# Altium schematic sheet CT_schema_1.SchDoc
size 391 x 258 mm
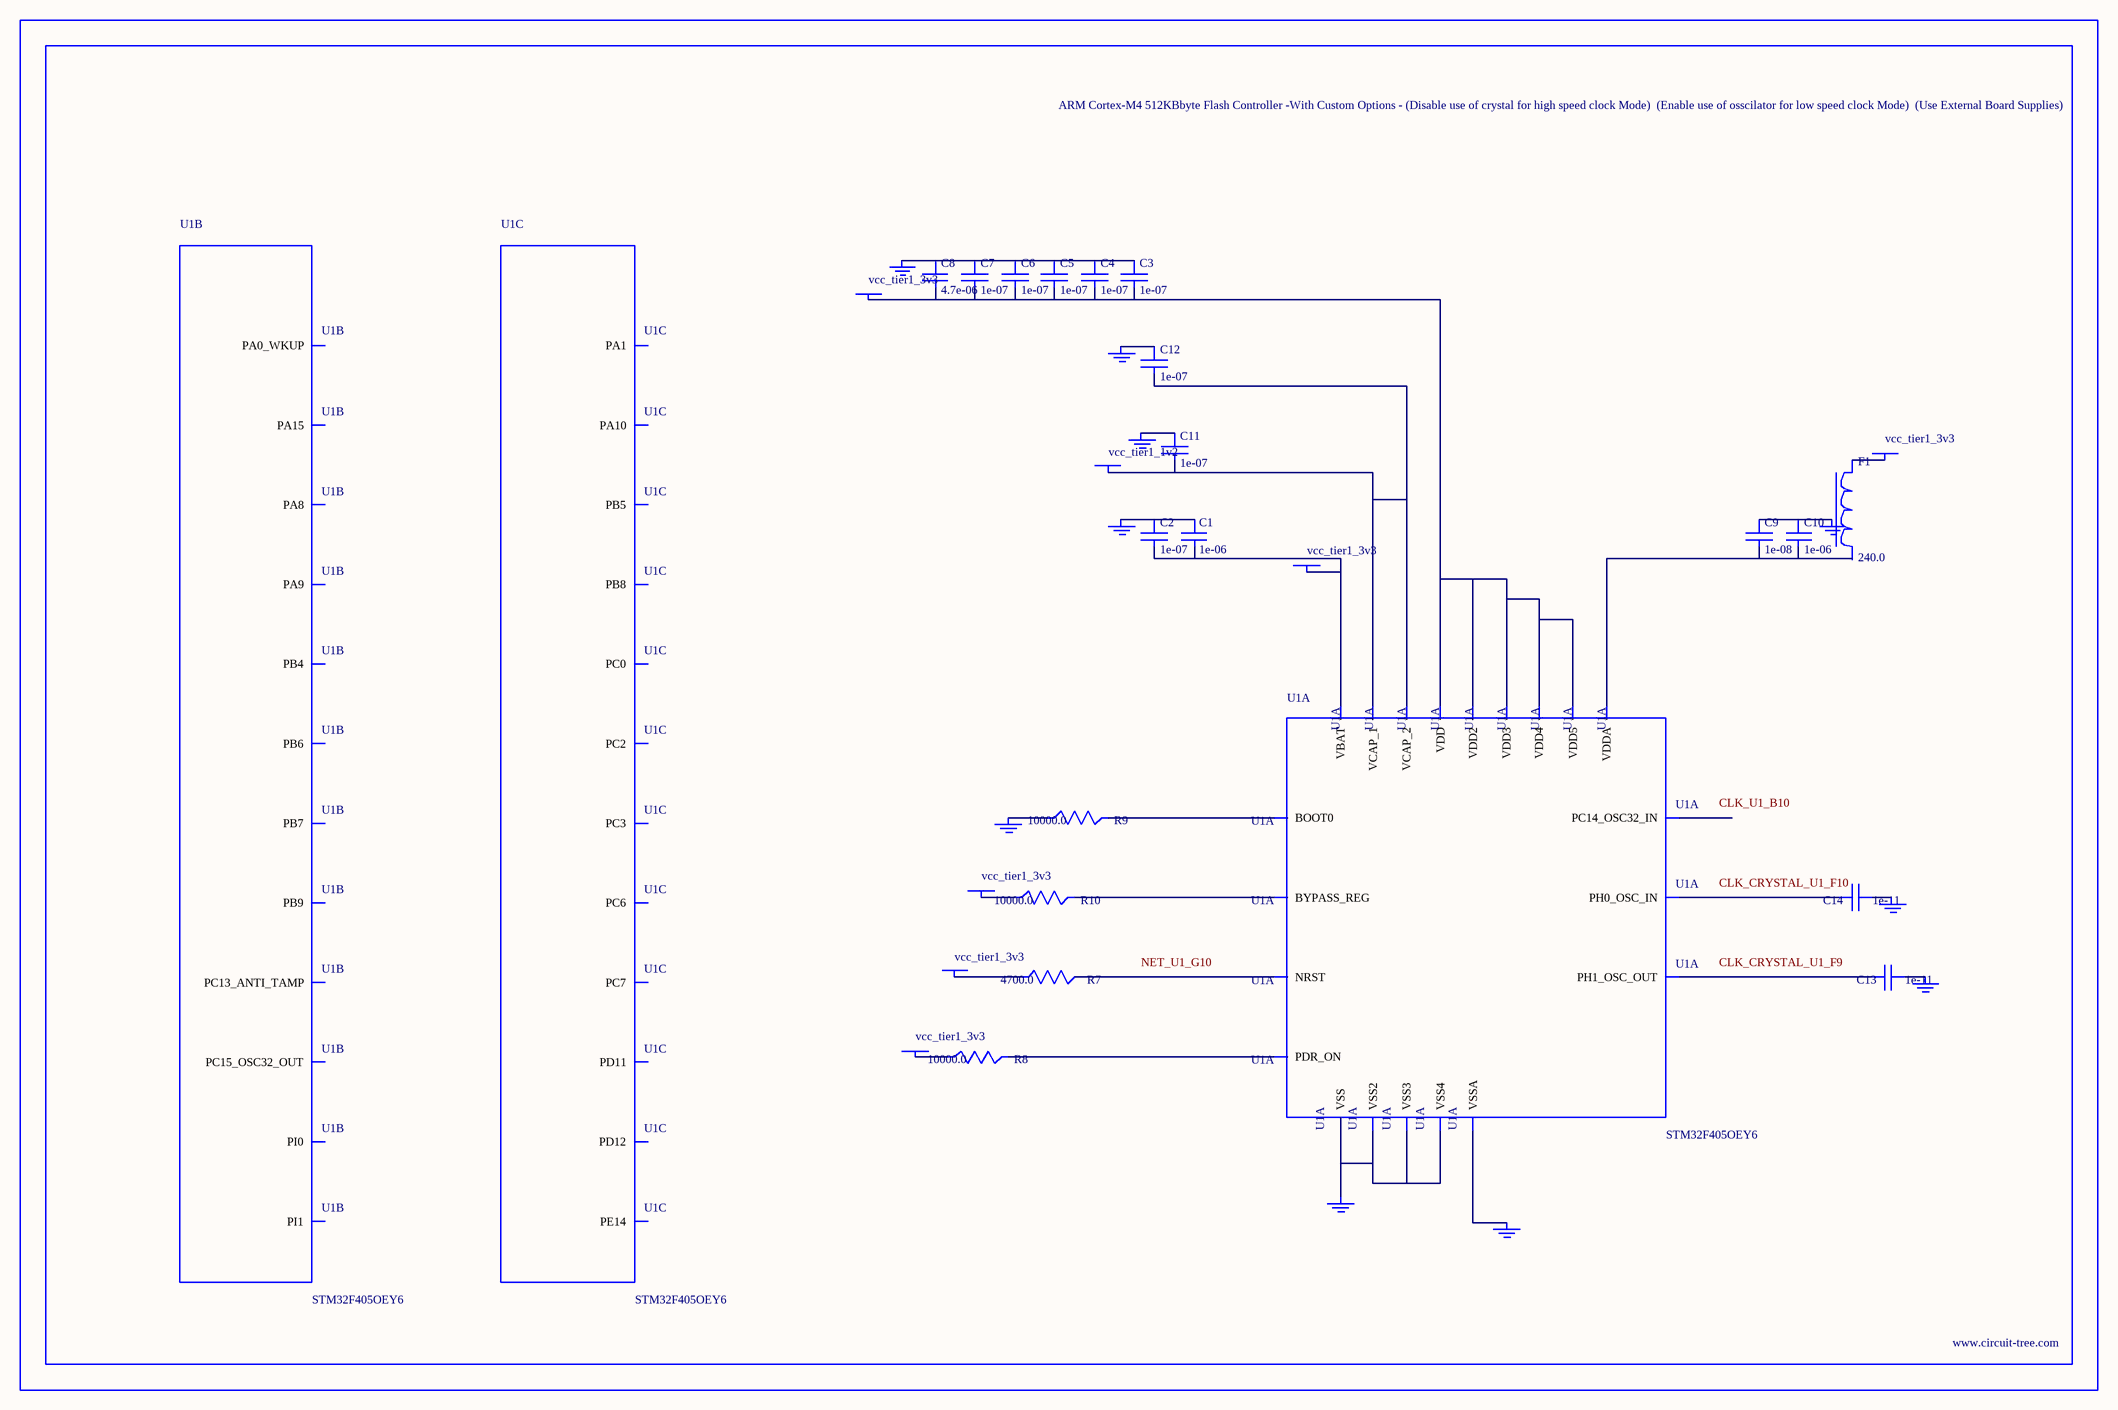
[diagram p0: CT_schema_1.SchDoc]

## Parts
BORDER0  (no value)
C1  1e-06  [C0603]
C2  1e-07  [C0603]
C3  1e-07  [C0603]
C4  1e-07  [C0603]
C5  1e-07  [C0603]
C6  1e-07  [C0603]
C7  1e-07  [C0603]
C8  4.7e-06  [C0603]
C9  1e-08  [C0603]
C10  1e-06  [C0603]
C11  1e-07  [C0402]
C12  1e-07  [C0402]
C13  1e-11  [C0402]
C14  1e-11  [C0402]
F1  240.0  [L0603]
GND_INSTANCE_0_0  (no value)
GND_INSTANCE_0_1  (no value)
GND_INSTANCE_0_2  (no value)
GND_INSTANCE_0_3  (no value)
GND_INSTANCE_0_4  (no value)
GND_INSTANCE_0_5  (no value)
GND_INSTANCE_0_6  (no value)
GND_INSTANCE_0_7  (no value)
GND_INSTANCE_0_8  (no value)
GND_INSTANCE_0_9  (no value)
POWER_INSTANCE_0_0  vcc_tier1_3v3
POWER_INSTANCE_0_1  vcc_tier1_3v3
POWER_INSTANCE_0_2  vcc_tier1_3v3
POWER_INSTANCE_0_3  vcc_tier1_3v3
POWER_INSTANCE_0_4  vcc_tier1_3v3
POWER_INSTANCE_0_5  vcc_tier1_1v2
POWER_INSTANCE_0_6  vcc_tier1_3v3
R7  4700.0  [R0603]
R8  10000.0  [R0603]
R9  10000.0  [R0603]
R10  10000.0  [R0603]
U1  STM32F405OEY6  [WLCSP90]  (parts A,B,C of 8)

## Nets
NetC1_1: C1.1 C2.1 GND_INSTANCE_0_0.0(GND)
NetC1_2: C1.2 C2.2 POWER_INSTANCE_0_0.0(PWR) U1.A10(VBAT)
NetC3_1: C3.1 C4.1 C5.1 C6.1 C7.1 C8.1 GND_INSTANCE_0_2.0(GND)
NetC3_2: C3.2 C4.2 C5.2 C6.2 C7.2 C8.2 POWER_INSTANCE_0_2.0(PWR) U1.A1(VDD) U1.B8(VDD2) U1.E4(VDD3) U1.E6(VDD4) U1.F7(VDD5)
NetC9_1: C9.1 C10.1 GND_INSTANCE_0_1.0(GND)
NetC9_2: C9.2 C10.2 U1.G9(VDDA)
NetC11_1: C11.1 GND_INSTANCE_0_4.0(GND)
NetC11_2: C11.2 C12.2 POWER_INSTANCE_0_5.0(PWR) U1.B1(VCAP_2) U1.F4(VCAP_1)
NetC12_1: C12.1 GND_INSTANCE_0_5.0(GND)
NetC13_1: C13.1 GND_INSTANCE_0_6.0(GND)
NetC13_2: C13.2 U1.F9(PH1_OSC_OUT)
NetC14_1: C14.1 GND_INSTANCE_0_7.0(GND)
NetC14_2: C14.2 U1.F10(PH0_OSC_IN)
NetF1_1: F1.1 POWER_INSTANCE_0_1.0(PWR)
NetGND_INSTANCE_0_3_0: GND_INSTANCE_0_3.0(GND) R9.1
NetGND_INSTANCE_0_8_0: GND_INSTANCE_0_8.0(GND) U1.H10(VSSA)
NetGND_INSTANCE_0_9_0: GND_INSTANCE_0_9.0(GND) U1.C9(VSS) U1.E5(VSS2) U1.E7(VSS3) U1.E8(VSS4)
NetPOWER_INSTANCE_0_3_0: POWER_INSTANCE_0_3.0(PWR) R8.1
NetPOWER_INSTANCE_0_4_0: POWER_INSTANCE_0_4.0(PWR) R10.1
NetPOWER_INSTANCE_0_6_0: POWER_INSTANCE_0_6.0(PWR) R7.1
NetR7_2: R7.2 U1.G10(NRST)
NetR8_2: R8.2 U1.A8(PDR_ON)
NetR9_2: R9.2 U1.A7(BOOT0)
NetR10_2: R10.2 U1.D9(BYPASS_REG)

Not connected (* = marked no-connect by the designer): F1 2; U1 A6(PB4) A9(PC13_ANTI_TAMP) B2(PI1) B3(PA15) B7(PB7) B9(PC15_OSC32_OUT) B10(PC14_OSC32_IN) C3(PI0) C7(PB6) C8(PB9) C10(PA0_WKUP) D1(PA8) D2(PA9) D3(PA10) D7(PB5) D8(PB8) D10(PC2) E1(PC7) E9(PC3) E10(PC0) F3(PC6) F5(PE14) F8(PA1) G1(PD11) G2(PD12)

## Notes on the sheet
- Labels drawn without touching a wire or pin: CLK_CRYSTAL_U1_F9, CLK_CRYSTAL_U1_F10, CLK_U1_B10, NET_U1_G10

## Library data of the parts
BORDER0 = BORDER_PAGE0
C1 C10 = C0603C105K3RACTU
C2-C7 = 06035C104K4Z2A
C8 = GRM188R6YA475KE15D
C9 = 06035C103K4Z2A
C11 C12 = C0402C104K3RACTU
C13 C14 = C0402C100K3GACTU
F1 = Z0603C241ASMST
GND_INSTANCE_0_0-GND_INSTANCE_0_9 = GND
POWER_INSTANCE_0_0-POWER_INSTANCE_0_6 = PWR
R7 = RC0603JR-074K7L
R8-R10 = RC0603JR-0710KL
